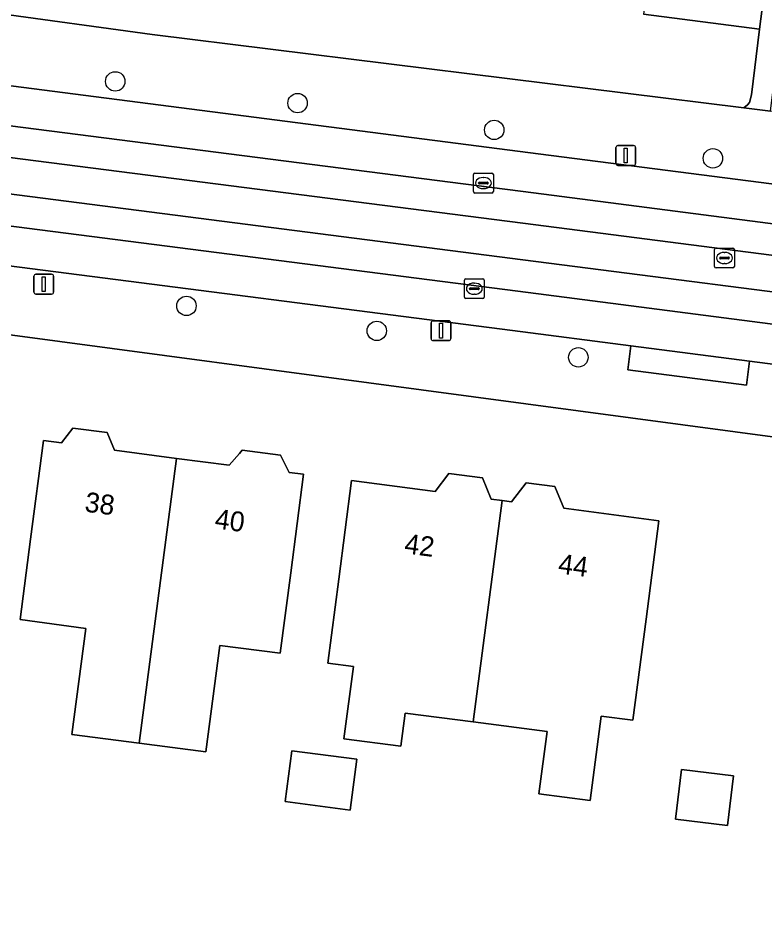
# Model space of a CAD drawing. Extents: x 161692 to 162379, y 380760 to 381678.
# Drawn here: x 161950.72 to 161988.33, y 381271.3 to 381316.74 of the extents above; entities that cross this region are included whole.
import ezdxf

# ---------------------------------------------------------------- set-up
doc = ezdxf.new("R2010")
doc.units = 0
for name, color, linetype in [('IMGEO_Boom', 7, 'Continuous'), ('IMGEO_Erf', 7, 'Continuous'), ('IMGEO_Kolk', 7, 'Continuous'), ('IMGEO_Lichtmast', 7, 'Continuous'), ('IMGEO_Pand', 7, 'Continuous'), ('IMGEO_Pand_nummerreeks', 7, 'Continuous'), ('IMGEO_Parkeervlak_open', 7, 'Continuous'), ('IMGEO_Rijbaan_lokaal_gesloten', 7, 'Continuous'), ('IMGEO_Rijbaan_lokaal_open', 7, 'Continuous'), ('IMGEO_Rioolput', 7, 'Continuous'), ('IMGEO_Voetpad_open', 7, 'Continuous')]:
    doc.layers.add(name, color=color, linetype=linetype)

msp = doc.modelspace()

# ---------------------------------------------------------------- linework, layer by layer
at = {"layer": 'IMGEO_Boom'}
for centre in [(161955.612, 381313.554), (161964.794, 381312.463), (161974.693, 381311.11), (161985.707, 381309.682), (161959.198, 381302.253), (161968.781, 381300.996), (161978.931, 381299.663)]:
    msp.add_circle(centre, 0.489, dxfattribs=at)
at = {"layer": 'IMGEO_Erf'}
for points in [[(161941.301, 381318.149), (161957.474, 381315.915), (161987.264, 381312.217), (161987.455, 381312.369), (161987.544, 381312.499), (161987.641, 381312.878), (161988.052, 381316.185), (161982.21, 381316.938)], [(161867.852, 381207.538), (161977.201, 381250), (161995.053, 381256.932), (162000, 381258.853), (162011.546, 381263.36), (162015.076, 381292.22), (162000, 381294.145), (161921.176, 381304.696), (161918.702, 381305.015), (161871.402, 381311.107)]]:
    msp.add_lwpolyline(points, dxfattribs=at)
for points in [[(161954.129, 381286.009), (161950.821, 381286.464), (161951.351, 381290.516), (161952, 381295.473), (161952.909, 381295.353), (161953.484, 381296.103), (161955.198, 381295.879), (161955.568, 381294.987), (161958.691, 381294.579), (161961.349, 381294.231), (161961.862, 381294.82), (161962.009, 381294.989), (161963.929, 381294.738), (161964.03, 381294.536), (161964.361, 381293.874), (161965.098, 381293.778), (161964.449, 381288.821), (161963.919, 381284.773), (161960.884, 381285.153), (161960.176, 381279.801), (161956.809, 381280.242), (161953.427, 381280.684)], [(161976.942, 381277.69), (161977.352, 381280.826), (161973.632, 381281.312), (161970.21, 381281.76), (161969.991, 381280.092), (161967.126, 381280.467), (161967.603, 381284.109), (161966.313, 381284.278), (161966.865, 381288.5), (161967.514, 381293.457), (161971.716, 381292.907), (161972.413, 381293.816), (161974.099, 381293.596), (161974.542, 381292.527), (161975.096, 381292.454), (161975.565, 381292.393), (161976.295, 381293.346), (161977.744, 381293.157), (161978.197, 381292.064), (161982.989, 381291.437), (161982.34, 381286.48), (161981.676, 381281.409), (161980.082, 381281.606), (161979.526, 381277.352)], [(161964.174, 381277.3), (161964.509, 381279.859), (161967.771, 381279.432), (161967.436, 381276.873)], [(161984.116, 381278.912), (161986.744, 381278.594), (161986.442, 381276.1), (161983.814, 381276.418)]]:
    msp.add_lwpolyline(points, close=True, dxfattribs=at)
at = {"layer": 'IMGEO_Kolk'}
for p, q in [((161973.649, 381308.008), (161973.649, 381308.86)), ((161973.724, 381308.934), (161974.576, 381308.934)), ((161974.137, 381308.714), (161974.162, 381308.714)), ((161974.65, 381308.86), (161974.65, 381308.008)), ((161973.908, 381308.428), (161973.908, 381308.44)), ((161974.346, 381308.391), (161973.948, 381308.391)), ((161973.951, 381308.477), (161974.349, 381308.477)), ((161974.16, 381308.154), (161974.135, 381308.154)), ((161974.392, 381308.44), (161974.392, 381308.428)), ((161974.576, 381307.934), (161973.724, 381307.934)), ((161973.265, 381303.619), (161974.117, 381303.619)), ((161973.19, 381302.693), (161973.19, 381303.545)), ((161973.449, 381303.113), (161973.449, 381303.125)), ((161973.492, 381303.162), (161973.89, 381303.162)), ((161973.678, 381303.399), (161973.703, 381303.399)), ((161973.933, 381303.125), (161973.933, 381303.113)), ((161974.191, 381303.545), (161974.191, 381302.693)), ((161973.887, 381303.076), (161973.489, 381303.076)), ((161973.701, 381302.839), (161973.676, 381302.839)), ((161974.117, 381302.619), (161973.265, 381302.619))]:
    msp.add_line(p, q, dxfattribs=at)
for points in [[(161973.649, 381308.008), (161973.649, 381308.86)], [(161973.724, 381308.934), (161974.576, 381308.934)], [(161974.65, 381308.86), (161974.65, 381308.008)], [(161974.576, 381307.934), (161973.724, 381307.934)], [(161973.265, 381303.619), (161974.117, 381303.619)], [(161973.19, 381302.693), (161973.19, 381303.545)], [(161974.191, 381303.545), (161974.191, 381302.693)], [(161974.117, 381302.619), (161973.265, 381302.619)]]:
    msp.add_lwpolyline(points, dxfattribs=at)
for centre, radius, start, end in [((161973.726, 381308.858), 0.0765, 91.552, 178.448), ((161973.726, 381308.858), 0.0765, 91.552, 178.448), ((161974.574, 381308.858), 0.0765, 1.552, 88.448), ((161974.574, 381308.858), 0.0765, 1.552, 88.448), ((161973.948, 381308.437), 0.0403, 85.8775, 175.7526), ((161973.945, 381308.427), 0.0366, 178.938, 274.7102), ((161974.349, 381308.434), 0.043, 264.8664, 352.4533), ((161974.353, 381308.439), 0.0386, 1.7309, 96.639), ((161973.726, 381308.01), 0.0765, 181.552, 268.448), ((161973.726, 381308.01), 0.0765, 181.552, 268.448), ((161974.574, 381308.01), 0.0765, 271.552, 358.448), ((161974.574, 381308.01), 0.0765, 271.552, 358.448), ((161973.267, 381303.543), 0.0765, 91.552, 178.448), ((161973.267, 381303.543), 0.0765, 91.552, 178.448), ((161974.115, 381303.543), 0.0765, 1.552, 88.448), ((161974.115, 381303.543), 0.0765, 1.552, 88.448), ((161973.489, 381303.122), 0.0403, 85.8775, 175.7526), ((161973.894, 381303.124), 0.0386, 1.7309, 96.639), ((161973.267, 381302.695), 0.0765, 181.552, 268.448), ((161973.267, 381302.695), 0.0765, 181.552, 268.448), ((161973.486, 381303.112), 0.0366, 178.938, 274.7102), ((161973.89, 381303.119), 0.043, 264.8664, 352.4533), ((161974.115, 381302.695), 0.0765, 271.552, 358.448), ((161974.115, 381302.695), 0.0765, 271.552, 358.448)]:
    msp.add_arc(centre, radius, start, end, dxfattribs=at)
for centre, major_axis, ratio, start_param, end_param in [((161974.136, 381308.434), (-0.387, 0.002), 0.722429, 4.712389, 7.853982), ((161974.161, 381308.434), (-0.39, 0.002), 0.717154, 1.570796, 4.712389), ((161973.677, 381303.119), (-0.387, 0.002), 0.722429, 4.712389, 7.853982), ((161973.702, 381303.119), (-0.39, 0.002), 0.717154, 1.570796, 4.712389)]:
    msp.add_ellipse(centre, major_axis=major_axis, ratio=ratio, start_param=start_param, end_param=end_param, dxfattribs=at)
at = {"layer": 'IMGEO_Lichtmast'}
for p, q in [((161980.825, 381309.424), (161980.825, 381310.224)), ((161980.825, 381310.224), (161980.825, 381309.424)), ((161980.925, 381310.324), (161981.715, 381310.324)), ((161981.715, 381310.324), (161980.925, 381310.324)), ((161981.815, 381310.224), (161981.815, 381309.424)), ((161981.815, 381309.424), (161981.815, 381310.224)), ((161981.715, 381309.324), (161980.925, 381309.324)), ((161980.925, 381309.324), (161981.715, 381309.324)), ((161951.517, 381302.945), (161951.517, 381303.745)), ((161951.517, 381303.745), (161951.517, 381302.945)), ((161951.617, 381303.845), (161952.407, 381303.845)), ((161952.407, 381303.845), (161951.617, 381303.845)), ((161952.507, 381303.745), (161952.507, 381302.945)), ((161952.507, 381302.945), (161952.507, 381303.745)), ((161952.407, 381302.845), (161951.617, 381302.845)), ((161951.617, 381302.845), (161952.407, 381302.845)), ((161971.517, 381300.605), (161971.517, 381301.405)), ((161971.517, 381301.405), (161971.517, 381300.605)), ((161971.617, 381301.505), (161972.407, 381301.505)), ((161972.407, 381301.505), (161971.617, 381301.505)), ((161972.507, 381301.405), (161972.507, 381300.605)), ((161972.507, 381300.605), (161972.507, 381301.405)), ((161972.407, 381300.505), (161971.617, 381300.505)), ((161971.617, 381300.505), (161972.407, 381300.505))]:
    msp.add_line(p, q, dxfattribs=at)
for points in [[(161981.245, 381310.199), (161981.395, 381310.199), (161981.395, 381309.449), (161981.245, 381309.449), (161981.245, 381310.199)], [(161951.937, 381303.72), (161952.087, 381303.72), (161952.087, 381302.97), (161951.937, 381302.97), (161951.937, 381303.72)], [(161971.937, 381301.38), (161972.087, 381301.38), (161972.087, 381300.63), (161971.937, 381300.63), (161971.937, 381301.38)]]:
    msp.add_lwpolyline(points, dxfattribs=at)
for centre, start, end in [((161980.925, 381310.224), 90, 180), ((161980.925, 381310.224), 90, 180), ((161981.715, 381310.224), 0, 90), ((161981.715, 381310.224), 360, 90), ((161980.925, 381309.424), 180, 270), ((161980.925, 381309.424), 180, 270), ((161981.715, 381309.424), 270, 0), ((161981.715, 381309.424), 270, 0), ((161951.617, 381303.745), 90, 180), ((161951.617, 381303.745), 90, 180), ((161952.407, 381303.745), 0, 90), ((161952.407, 381303.745), 360, 90), ((161951.617, 381302.945), 180, 270), ((161951.617, 381302.945), 180, 270), ((161952.407, 381302.945), 270, 0), ((161952.407, 381302.945), 270, 0), ((161971.617, 381301.405), 90, 180), ((161971.617, 381301.405), 90, 180), ((161972.407, 381301.405), 0, 90), ((161972.407, 381301.405), 360, 90), ((161971.617, 381300.605), 180, 270), ((161971.617, 381300.605), 180, 270), ((161972.407, 381300.605), 270, 0), ((161972.407, 381300.605), 270, 0)]:
    msp.add_arc(centre, 0.1, start, end, dxfattribs=at)
at = {"layer": 'IMGEO_Pand'}
for points in [[(161984.016, 381330.956), (161982.21, 381316.938), (161988.052, 381316.185), (161988.691, 381321.145), (161989.064, 381324.039), (161989.152, 381324.726), (161989.454, 381327.073), (161986.047, 381327.512), (161986.45, 381330.642)], [(161956.809, 381280.242), (161958.691, 381294.579), (161955.568, 381294.987), (161955.198, 381295.879), (161953.484, 381296.103), (161952.909, 381295.353), (161952, 381295.473), (161951.351, 381290.516), (161950.821, 381286.464), (161954.129, 381286.009), (161953.427, 381280.684)], [(161961.862, 381294.82), (161961.349, 381294.231), (161958.691, 381294.579), (161956.809, 381280.242), (161960.176, 381279.801), (161960.884, 381285.153), (161963.919, 381284.773), (161964.449, 381288.821), (161965.098, 381293.778), (161964.361, 381293.874), (161964.03, 381294.536), (161963.929, 381294.738), (161962.009, 381294.989)], [(161973.632, 381281.312), (161975.096, 381292.454), (161974.542, 381292.527), (161974.099, 381293.596), (161972.413, 381293.816), (161971.716, 381292.907), (161967.514, 381293.457), (161966.865, 381288.5), (161966.313, 381284.278), (161967.603, 381284.109), (161967.126, 381280.467), (161969.991, 381280.092), (161970.21, 381281.76)], [(161973.632, 381281.312), (161977.352, 381280.826), (161976.942, 381277.69), (161979.526, 381277.352), (161980.082, 381281.606), (161981.676, 381281.409), (161982.34, 381286.48), (161982.989, 381291.437), (161978.197, 381292.064), (161977.744, 381293.157), (161976.295, 381293.346), (161975.565, 381292.393), (161975.096, 381292.454)], [(161964.174, 381277.3), (161967.436, 381276.873), (161967.771, 381279.432), (161964.509, 381279.859)], [(161983.814, 381276.418), (161986.442, 381276.1), (161986.744, 381278.594), (161984.116, 381278.912)]]:
    msp.add_lwpolyline(points, close=True, dxfattribs=at)
at = {"layer": 'IMGEO_Parkeervlak_open'}
for points in [[(162014.029, 381298.061), (162013.612, 381298.115), (161975.89, 381302.987), (161949.317, 381306.399), (161923.115, 381309.763)], [(161925.957, 381307.387), (161975.622, 381301.017), (161981.576, 381300.237), (161987.551, 381299.472), (162010.923, 381296.455)]]:
    msp.add_lwpolyline(points, dxfattribs=at)
at = {"layer": 'IMGEO_Rijbaan_lokaal_gesloten'}
for points in [[(161938.099, 381314.908), (161875.004, 381322.955), (161874.726, 381320.753), (161937.716, 381312.93), (161976.665, 381307.938), (162014.292, 381303.079), (162014.626, 381303.036)], [(162011.888, 381305.414), (161977.562, 381309.831), (161938.099, 381314.908)]]:
    msp.add_lwpolyline(points, dxfattribs=at)
for points in [[(161937.716, 381312.93), (161874.726, 381320.753), (161874.551, 381319.364), (161924.33, 381313.049), (161976.129, 381306.423), (162014.081, 381301.54), (162014.292, 381303.079), (161976.665, 381307.938)], [(161924.113, 381311.254), (161874.322, 381317.556), (161874.117, 381315.93), (161876.187, 381315.72), (161917.21, 381310.5), (161917.275, 381310.497), (161923.115, 381309.763), (161949.317, 381306.399), (161975.89, 381302.987), (162013.612, 381298.115), (162013.834, 381299.74), (161976.139, 381304.58)]]:
    msp.add_lwpolyline(points, close=True, dxfattribs=at)
at = {"layer": 'IMGEO_Rijbaan_lokaal_open'}
msp.add_lwpolyline([(161874.551, 381319.364), (161874.322, 381317.556), (161924.113, 381311.254), (161976.139, 381304.58), (162013.834, 381299.74), (162014.081, 381301.54), (161976.129, 381306.423), (161924.33, 381313.049)], close=True, dxfattribs=at)
at = {"layer": 'IMGEO_Rioolput'}
for p, q in [((161985.787, 381304.238), (161985.787, 381305.09)), ((161985.862, 381305.164), (161986.714, 381305.164)), ((161986.275, 381304.944), (161986.3, 381304.944)), ((161986.788, 381305.09), (161986.788, 381304.238)), ((161986.046, 381304.658), (161986.046, 381304.67)), ((161986.484, 381304.621), (161986.086, 381304.621)), ((161986.089, 381304.707), (161986.487, 381304.707)), ((161986.53, 381304.67), (161986.53, 381304.658)), ((161986.714, 381304.164), (161985.862, 381304.164)), ((161986.298, 381304.384), (161986.273, 381304.384))]:
    msp.add_line(p, q, dxfattribs=at)
for points in [[(161985.787, 381304.238), (161985.787, 381305.09)], [(161985.862, 381305.164), (161986.714, 381305.164)], [(161986.788, 381305.09), (161986.788, 381304.238)], [(161986.714, 381304.164), (161985.862, 381304.164)]]:
    msp.add_lwpolyline(points, dxfattribs=at)
for centre, radius, start, end in [((161985.864, 381305.088), 0.0765, 91.552, 178.448), ((161985.864, 381305.088), 0.0765, 91.552, 178.448), ((161986.712, 381305.088), 0.0765, 1.552, 88.448), ((161986.712, 381305.088), 0.0765, 1.552, 88.448), ((161986.086, 381304.667), 0.0403, 85.8775, 175.7526), ((161986.083, 381304.657), 0.0366, 178.938, 274.7102), ((161986.487, 381304.664), 0.043, 264.8664, 352.4533), ((161986.491, 381304.669), 0.0386, 1.7309, 96.639), ((161985.864, 381304.24), 0.0765, 181.552, 268.448), ((161985.864, 381304.24), 0.0765, 181.552, 268.448), ((161986.712, 381304.24), 0.0765, 271.552, 358.448), ((161986.712, 381304.24), 0.0765, 271.552, 358.448)]:
    msp.add_arc(centre, radius, start, end, dxfattribs=at)
for centre, major_axis, ratio, start_param, end_param in [((161986.274, 381304.664), (-0.387, 0.002), 0.722429, 4.712389, 7.853982), ((161986.299, 381304.664), (-0.39, 0.002), 0.717154, 1.570796, 4.712389)]:
    msp.add_ellipse(centre, major_axis=major_axis, ratio=ratio, start_param=start_param, end_param=end_param, dxfattribs=at)
at = {"layer": 'IMGEO_Voetpad_open'}
for points in [[(161832.538, 381328.345), (161858.081, 381325.137), (161875.004, 381322.955), (161938.099, 381314.908), (161977.562, 381309.831), (162011.888, 381305.414)], [(161988.691, 381321.145), (161988.052, 381316.185), (161987.641, 381312.878), (161987.544, 381312.499), (161987.455, 381312.369), (161987.264, 381312.217), (161988.599, 381312.051), (161989.105, 381316.129), (161989.744, 381321.088)], [(162012.53, 381305.017), (162017.252, 381308.434), (162007.146, 381309.715), (161997.312, 381310.962), (161994.487, 381311.32), (161988.599, 381312.051), (161987.264, 381312.217), (161957.474, 381315.915), (161941.301, 381318.149)], [(161867.278, 381309.693), (161868.344, 381309.528), (161871.402, 381311.107), (161918.702, 381305.015), (161921.176, 381304.696), (162000, 381294.145), (162015.076, 381292.22), (162011.546, 381263.36), (162011.205, 381260.006), (162013.191, 381260.844), (162013.658, 381259.636)], [(162010.923, 381296.455), (161987.551, 381299.472), (161987.391, 381298.267), (161981.42, 381299.042), (161981.576, 381300.237), (161975.622, 381301.017), (161925.957, 381307.387)]]:
    msp.add_lwpolyline(points, dxfattribs=at)
msp.add_lwpolyline([(161981.576, 381300.237), (161981.42, 381299.042), (161987.391, 381298.267), (161987.551, 381299.472)], close=True, dxfattribs=at)

# ---------------------------------------------------------------- texts
at = {"layer": 'IMGEO_Pand_nummerreeks'}
for s, rotation, p in [('38', 352.6264, (161954.037, 381291.902)), ('40', 352.626, (161960.585, 381291.055)), ('42', 352.5631, (161970.136, 381289.806)), ('44', 352.5631, (161977.877, 381288.796))]:
    msp.add_text(s, height=1, rotation=rotation, dxfattribs=at).set_placement(p)

doc.saveas('drawing.dxf')
